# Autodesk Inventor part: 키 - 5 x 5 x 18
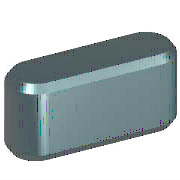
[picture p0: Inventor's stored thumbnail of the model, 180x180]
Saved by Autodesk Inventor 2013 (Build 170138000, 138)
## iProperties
Created: 2012-02
Part Number: 키 - 5 x 5 x 18
Material: 강철, 연강
Description: 키 및 해당 키홈
Document SubType Name: Modeling
Standard: KS B 1311
Designer: mduedu
Standards Organization: KS
Language: ko-KR
Size Designation: 5 x 5 x 18
Categories: <MemberInstance><Categories><Category DisplayName="샤프트 부품" InternalName="7f7aeb1f-a693-4053-b835-cee3144e0d98" Mnemonic="SHFT"><Category DisplayName="키" Interna
Density: 7.86 g/cm^3
Mass: 3.27476 g
Surface Area: 3.57848 cm^2
Volume: 0.416636 cm^3
IsCustomPart: 1
Author: mduedu
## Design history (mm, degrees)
workplane "Work Plane1"
workplane "Work Plane2"
sketch "스케치1"
  geometry: L1 (2.5, 2.5)-(15.5, 2.5); L2 (15.5, -2.5)-(2.5, -2.5); L3 (0, 9.4)-(0, -7.4) reference; L4 (-5, 0)-(30, 0) reference; L5 (18, 0)-(18, 7); A1 r 2.5 centre (2.5, 0) between (2.5, 2.5) and (2.5, -2.5); A2 r 2.5 centre (15.5, 0) between (15.5, -2.5) and (15.5, 2.5)
  constraints: 6 end point, 5 point on circle, 4 tangent, 3 point on line, 2 centre point, 1 horizontal, 1 parallel, 1 perpendicular
  dimensions: "d0" = 2.5 radius of A1 (= 0.5 x PB); "d13" = 2.5 radius of A2 (= 0.5 x PB); "d14" = 18 distance between parallel lines of L5 L3 (= NLG)
extrude "본체1" new body sketch "스케치1" taper "d3" = 0 deg; stored distance "d4" = 10
workplane "Work Plane3"
body "Solid1"
chamfer "모따기1" distance "d8" = 0.4 (= PHH); stored, may be unused: second distance "d9" = 0.4 (= PHH), angle "d15" = 45 deg
other parameters: "d1" = -3 (= -PNT), "d2" = 2 (= PH - PNT), "NLG" = 18 [user parameter; used in 3 equation terms], "PB" = 5 [user parameter; used in 2 equation terms], "PNT" = 3 [user parameter; used in 2 equation terms], "PH" = 5 [user parameter; used in 1 equation term], "PHH" = 0.4 [user parameter; used in 2 equation terms], "d10" = 0, "d16" = 0, "d17" = 0, "d18" = 0, "WDMIN" = 12 [user parameter], "PLB2" = 18 (= NLG) [user parameter], "WDMAX" = 17 [user parameter], "PLB1" = 18 (= NLG) [user parameter], "RR" = 0.16 [user parameter], "PUEB" = 2.3 [user parameter]
